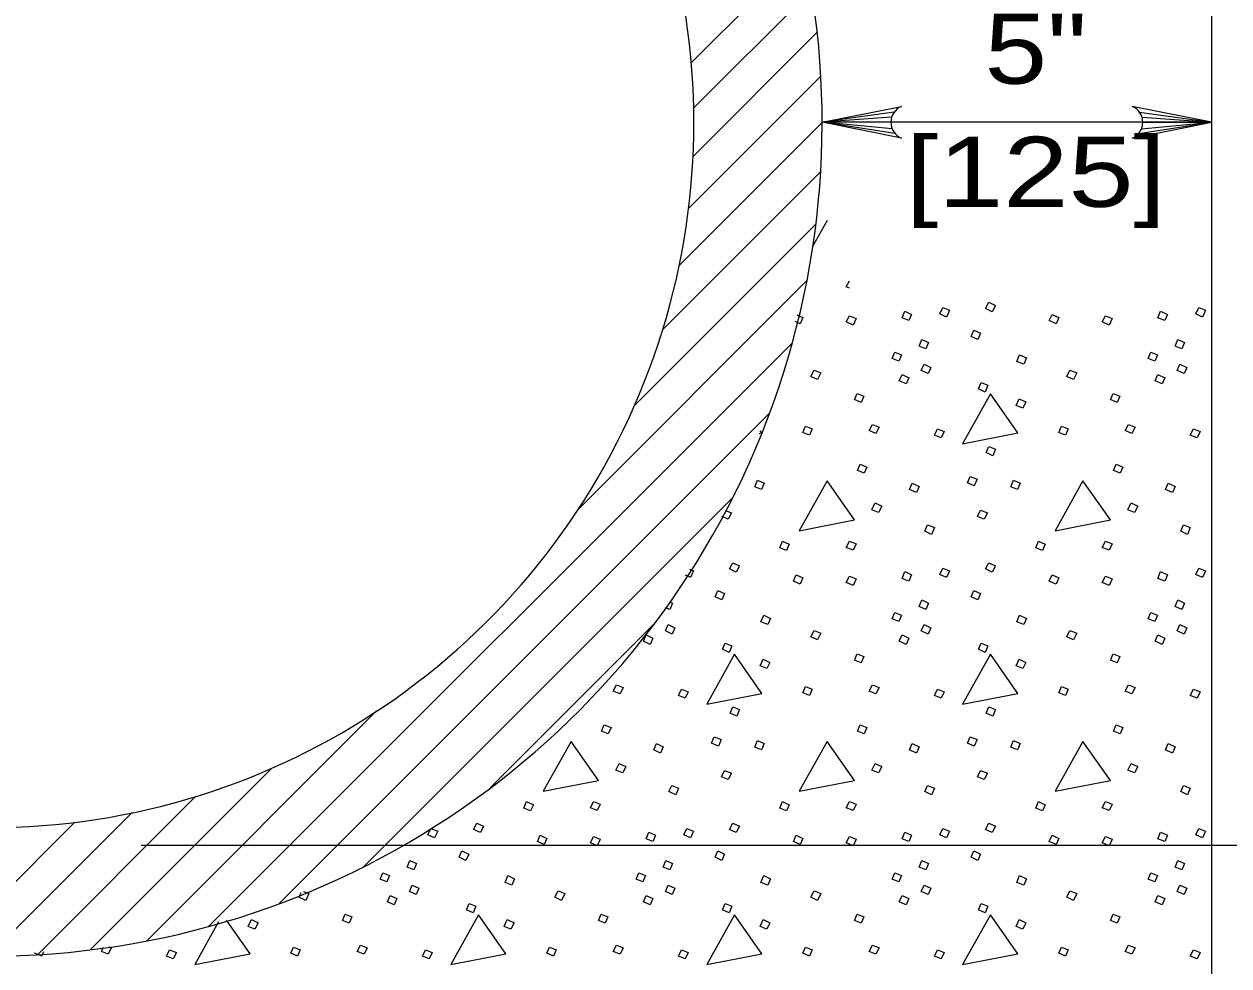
# Model space of a CAD drawing. Extents: x 1036.7 to 1070.7, y 883.9 to 905.9.
# Drawn here: x 1054.169 to 1056.851, y 894.74 to 896.836 of the extents above; entities that cross this region are included whole.
import ezdxf
from ezdxf.enums import TextEntityAlignment as Align

# ---------------------------------------------------------------- set-up
doc = ezdxf.new("R2010")
doc.units = 0
doc.header["$LTSCALE"] = 0.062
doc.layers.add('1', color=7, linetype='Continuous', lineweight=13)

msp = doc.modelspace()

# ---------------------------------------------------------------- linework, layer by layer
at = {"layer": '1'}
for p, q in [((1055.65425, 896.74975), (1055.90517, 897.00058)), ((1055.65967, 896.64908), (1055.92167, 896.911)), ((1055.65833, 896.54175), (1055.93425, 896.81758)), ((1055.64792, 896.42533), (1055.94225, 896.71958)), ((1055.62667, 896.29817), (1055.94508, 896.61633)), ((1056.106, 896.64), (1055.94575, 896.61758)), ((1056.1005, 896.62892), (1055.94575, 896.61758)), ((1056.09892, 896.61758), (1055.94575, 896.61758)), ((1056.10175, 896.60325), (1055.94575, 896.61758)), ((1056.10783, 896.59283), (1055.94575, 896.61758)), ((1056.65058, 896.59283), (1056.81275, 896.61758)), ((1056.6525, 896.64), (1056.81275, 896.61758)), ((1056.65675, 896.60325), (1056.81275, 896.61758)), ((1056.65792, 896.62892), (1056.81275, 896.61758)), ((1056.65958, 896.61758), (1056.81275, 896.61758)), ((1055.59083, 896.15625), (1055.94175, 896.50708)), ((1055.52825, 895.98758), (1055.93108, 896.39033)), ((1055.95667, 896.399), (1055.9235, 896.33958)), ((1055.40108, 895.75442), (1055.91125, 896.26458)), ((1054.58083, 894.82842), (1055.87942, 896.12683)), ((1054.73742, 894.87892), (1055.82817, 895.9695)), ((1054.92558, 894.96108), (1055.74567, 895.781)), ((1055.20725, 895.13667), (1055.57117, 895.5005)), ((1054.44258, 894.79608), (1054.95308, 895.30658)), ((1054.31633, 894.77583), (1054.72, 895.17942)), ((1054.19933, 894.76483), (1054.552, 895.1175)), ((1054.09, 894.7615), (1054.40967, 895.08117)), ((1053.987, 894.7645), (1054.28267, 895.06017)), ((1058.42608, 895.00783), (1054.42967, 895.00783))]:
    msp.add_line(p, q, dxfattribs=at)
at = {"layer": '1', "lineweight": 25}
msp.add_lwpolyline([(1056.21542, 900.486), (1056.21542, 899.32858), (1056.81275, 899.32858), (1056.81275, 893.80992)], dxfattribs=at)
at = {"layer": '1'}
for points in [[(1056.12275, 896.58225), (1055.94575, 896.61758), (1056.12275, 896.653)], [(1056.63575, 896.58225), (1056.81275, 896.61758), (1056.63575, 896.653)], [(1056.81275, 896.61758), (1056.53767, 896.61758), (1055.94575, 896.61758)], [(1056.00642, 896.24833), (1055.99958, 896.25108), (1056.00642, 896.26475)], [(1055.88975, 896.18908), (1055.90267, 896.18308), (1055.89667, 896.16917), (1055.88608, 896.17408)], [(1055.80567, 895.92508), (1055.81167, 895.92625), (1055.80817, 895.93117)], [(1055.73067, 895.75358), (1055.74375, 895.74833), (1055.73675, 895.73442), (1055.72242, 895.74017)], [(1055.65033, 895.62317), (1055.65975, 895.61942), (1055.65275, 895.60442), (1055.64192, 895.6095)], [(1055.60575, 895.55075), (1055.61275, 895.5475), (1055.60683, 895.5335), (1055.59742, 895.53725)], [(1054.7915, 894.9055), (1054.80317, 894.90083), (1054.79617, 894.88583), (1054.78117, 894.89283), (1054.7865, 894.90342)], [(1054.60217, 894.83767), (1054.54933, 894.74292), (1054.67225, 894.76692), (1054.61967, 894.84192)], [(1054.21233, 894.77117), (1054.20842, 894.76192), (1054.1935, 894.76792), (1054.19417, 894.76975)], [(1054.357, 894.7825), (1054.36342, 894.77992), (1054.35642, 894.76592), (1054.34142, 894.77192), (1054.34625, 894.78167)]]:
    msp.add_lwpolyline(points, dxfattribs=at)
for points in [[(1056.3165, 896.21708), (1056.33142, 896.21008), (1056.32442, 896.19608), (1056.3095, 896.20308)], [(1056.12958, 896.19708), (1056.1445, 896.19008), (1056.13858, 896.17617), (1056.12358, 896.18208)], [(1056.2145, 896.20508), (1056.2295, 896.19908), (1056.2225, 896.18408), (1056.2075, 896.19108)], [(1056.45742, 896.19008), (1056.47242, 896.18308), (1056.46642, 896.16917), (1056.45142, 896.17617)], [(1056.69925, 896.19708), (1056.71425, 896.19008), (1056.70825, 896.17617), (1056.69325, 896.18208)], [(1056.78425, 896.20508), (1056.79925, 896.19908), (1056.79225, 896.18408), (1056.77725, 896.19108)], [(1056.00658, 896.18708), (1056.02158, 896.18108), (1056.01458, 896.16617), (1055.99958, 896.17317)], [(1056.57633, 896.18708), (1056.59133, 896.18108), (1056.58433, 896.16617), (1056.56933, 896.17317)], [(1056.1675, 896.13417), (1056.1825, 896.12717), (1056.1765, 896.11317), (1056.1615, 896.11917)], [(1056.2835, 896.15517), (1056.2985, 896.14817), (1056.2925, 896.13417), (1056.2775, 896.14117)], [(1056.73725, 896.13417), (1056.75225, 896.12717), (1056.74625, 896.11317), (1056.73125, 896.11917)], [(1056.10758, 896.10617), (1056.12258, 896.10017), (1056.11658, 896.08617), (1056.10158, 896.09217)], [(1056.38542, 896.10017), (1056.40042, 896.09317), (1056.39442, 896.07917), (1056.37942, 896.08517)], [(1056.67725, 896.10617), (1056.69225, 896.10017), (1056.68625, 896.08617), (1056.67125, 896.09217)], [(1055.92767, 896.06617), (1055.94267, 896.06017), (1055.93567, 896.04517), (1055.92067, 896.05217)], [(1056.12358, 896.05617), (1056.13858, 896.04917), (1056.13258, 896.03517), (1056.11758, 896.04217)], [(1056.1725, 896.07917), (1056.1875, 896.07217), (1056.1815, 896.05817), (1056.1665, 896.06517)], [(1056.49733, 896.06617), (1056.51233, 896.06017), (1056.50533, 896.04517), (1056.49042, 896.05217)], [(1056.69325, 896.05617), (1056.70825, 896.04917), (1056.70225, 896.03517), (1056.68725, 896.04217)], [(1056.74225, 896.07917), (1056.75725, 896.07217), (1056.75125, 896.05817), (1056.73625, 896.06517)], [(1056.2995, 896.03817), (1056.31442, 896.03225), (1056.3085, 896.01725), (1056.2935, 896.02425)], [(1056.02358, 896.01425), (1056.03858, 896.00825), (1056.03258, 895.99425), (1056.01758, 896.00025)], [(1056.32042, 896.01325), (1056.2585, 895.90225), (1056.38142, 895.92625)], [(1056.38442, 896.00225), (1056.39942, 895.99525), (1056.39242, 895.98125), (1056.37742, 895.98725)], [(1056.59333, 896.01425), (1056.60833, 896.00825), (1056.60233, 895.99425), (1056.58733, 896.00025)], [(1055.90867, 895.94125), (1055.92367, 895.93525), (1055.91767, 895.92125), (1055.90267, 895.92725)], [(1056.05758, 895.94525), (1056.07258, 895.93925), (1056.06558, 895.92525), (1056.05058, 895.93125)], [(1056.2025, 895.93525), (1056.2175, 895.92925), (1056.2105, 895.91525), (1056.1955, 895.92125)], [(1056.47842, 895.94125), (1056.49333, 895.93525), (1056.48742, 895.92125), (1056.47242, 895.92725)], [(1056.62733, 895.94525), (1056.64233, 895.93925), (1056.63533, 895.92525), (1056.62033, 895.93125)], [(1056.77225, 895.93525), (1056.78725, 895.92925), (1056.78025, 895.91525), (1056.76525, 895.92125)], [(1056.3165, 895.89625), (1056.33142, 895.89033), (1056.32542, 895.87533), (1056.3105, 895.88233)], [(1056.03058, 895.85633), (1056.04558, 895.85033), (1056.03958, 895.83633), (1056.02458, 895.84233)], [(1056.60033, 895.85633), (1056.61533, 895.85033), (1056.60933, 895.83633), (1056.59433, 895.84233)], [(1055.80167, 895.82133), (1055.81667, 895.81433), (1055.81067, 895.80033), (1055.79567, 895.80633)], [(1055.95667, 895.81933), (1055.89467, 895.70842), (1056.01758, 895.73242)], [(1056.1465, 895.81433), (1056.1615, 895.80733), (1056.1555, 895.79333), (1056.1405, 895.80033)], [(1056.2755, 895.82933), (1056.2905, 895.82333), (1056.2845, 895.80833), (1056.2695, 895.81533)], [(1056.37142, 895.82133), (1056.38642, 895.81433), (1056.38042, 895.80033), (1056.36542, 895.80633)], [(1056.52633, 895.81933), (1056.46442, 895.70842), (1056.58733, 895.73242)], [(1056.71625, 895.81433), (1056.73125, 895.80733), (1056.72525, 895.79333), (1056.71025, 895.80033)], [(1056.06358, 895.77033), (1056.07858, 895.76333), (1056.07158, 895.74933), (1056.05658, 895.75533)], [(1056.63333, 895.77033), (1056.64833, 895.76333), (1056.64133, 895.74933), (1056.62633, 895.75533)], [(1056.2985, 895.75433), (1056.3135, 895.74833), (1056.3065, 895.73442), (1056.2915, 895.74042)], [(1056.1805, 895.72142), (1056.1955, 895.71542), (1056.1895, 895.70042), (1056.1745, 895.70742)], [(1056.75025, 895.72142), (1056.76525, 895.71542), (1056.75925, 895.70042), (1056.74425, 895.70742)], [(1055.85767, 895.68542), (1055.87267, 895.67842), (1055.86667, 895.66442), (1055.85167, 895.67042)], [(1056.00658, 895.68542), (1056.02158, 895.67942), (1056.01458, 895.66542), (1055.99958, 895.67142)], [(1056.42742, 895.68542), (1056.44242, 895.67842), (1056.43642, 895.66442), (1056.42142, 895.67042)], [(1056.57633, 895.68542), (1056.59133, 895.67942), (1056.58433, 895.66542), (1056.56933, 895.67142)], [(1055.74675, 895.63742), (1055.76175, 895.63042), (1055.75475, 895.61642), (1055.73975, 895.62342)], [(1056.2145, 895.62542), (1056.2295, 895.61942), (1056.2225, 895.60442), (1056.2075, 895.61142)], [(1056.3165, 895.63742), (1056.33142, 895.63042), (1056.32442, 895.61642), (1056.3095, 895.62342)], [(1056.78425, 895.62542), (1056.79925, 895.61942), (1056.79225, 895.60442), (1056.77725, 895.61142)], [(1055.88767, 895.61042), (1055.90267, 895.60342), (1055.89667, 895.5895), (1055.88167, 895.5965)], [(1056.00658, 895.60742), (1056.02158, 895.60142), (1056.01458, 895.5865), (1055.99958, 895.5935)], [(1056.12958, 895.61742), (1056.1445, 895.61042), (1056.13858, 895.5965), (1056.12358, 895.60242)], [(1056.45742, 895.61042), (1056.47242, 895.60342), (1056.46642, 895.5895), (1056.45142, 895.5965)], [(1056.57633, 895.60742), (1056.59133, 895.60142), (1056.58433, 895.5865), (1056.56933, 895.5935)], [(1056.69925, 895.61742), (1056.71425, 895.61042), (1056.70825, 895.5965), (1056.69325, 895.60242)], [(1055.71375, 895.5755), (1055.72875, 895.5685), (1055.72275, 895.5545), (1055.70775, 895.5615)], [(1056.2835, 895.5755), (1056.2985, 895.5685), (1056.2925, 895.5545), (1056.2775, 895.5615)], [(1056.1675, 895.5545), (1056.1825, 895.5475), (1056.1765, 895.5335), (1056.1615, 895.5395)], [(1056.73725, 895.5545), (1056.75225, 895.5475), (1056.74625, 895.5335), (1056.73125, 895.5395)], [(1055.81567, 895.5205), (1055.83067, 895.5135), (1055.82467, 895.4995), (1055.80967, 895.5055)], [(1056.10758, 895.5265), (1056.12258, 895.5205), (1056.11658, 895.5065), (1056.10158, 895.5125)], [(1056.38542, 895.5205), (1056.40042, 895.5135), (1056.39442, 895.4995), (1056.37942, 895.5055)], [(1056.67725, 895.5265), (1056.69225, 895.5205), (1056.68625, 895.5065), (1056.67125, 895.5125)], [(1055.60283, 895.4995), (1055.61775, 895.4925), (1055.61175, 895.4785), (1055.59683, 895.4855)], [(1056.1725, 895.4995), (1056.1875, 895.4925), (1056.1815, 895.4785), (1056.1665, 895.4855)], [(1056.74225, 895.4995), (1056.75725, 895.4925), (1056.75125, 895.4785), (1056.73625, 895.4855)], [(1055.55383, 895.4765), (1055.56883, 895.4695), (1055.56283, 895.4555), (1055.54783, 895.4625)], [(1055.92767, 895.4865), (1055.94267, 895.4805), (1055.93567, 895.4655), (1055.92067, 895.4725)], [(1056.12358, 895.4765), (1056.13858, 895.4695), (1056.13258, 895.4555), (1056.11758, 895.4625)], [(1056.49733, 895.4865), (1056.51233, 895.4805), (1056.50533, 895.4655), (1056.49042, 895.4725)], [(1056.69325, 895.4765), (1056.70825, 895.4695), (1056.70225, 895.4555), (1056.68725, 895.4625)], [(1055.72975, 895.4585), (1055.74475, 895.45258), (1055.73875, 895.43758), (1055.72375, 895.44458)], [(1056.2995, 895.4585), (1056.31442, 895.45258), (1056.3085, 895.43758), (1056.2935, 895.44458)], [(1055.75075, 895.43358), (1055.68875, 895.32258), (1055.81167, 895.34658)], [(1055.81467, 895.42258), (1055.82967, 895.41558), (1055.82267, 895.40158), (1055.80767, 895.40758)], [(1056.02358, 895.43458), (1056.03858, 895.42858), (1056.03258, 895.41458), (1056.01758, 895.42058)], [(1056.32042, 895.43358), (1056.2585, 895.32258), (1056.38142, 895.34658)], [(1056.38442, 895.42258), (1056.39942, 895.41558), (1056.39242, 895.40158), (1056.37742, 895.40758)], [(1056.59333, 895.43458), (1056.60833, 895.42858), (1056.60233, 895.41458), (1056.58733, 895.42058)], [(1055.48783, 895.36558), (1055.50283, 895.35958), (1055.49583, 895.34558), (1055.48083, 895.35158)], [(1055.90867, 895.36158), (1055.92367, 895.35558), (1055.91767, 895.34158), (1055.90267, 895.34758)], [(1056.05758, 895.36558), (1056.07258, 895.35958), (1056.06558, 895.34558), (1056.05058, 895.35158)], [(1056.47842, 895.36158), (1056.49333, 895.35558), (1056.48742, 895.34158), (1056.47242, 895.34758)], [(1056.62733, 895.36558), (1056.64233, 895.35958), (1056.63533, 895.34558), (1056.62033, 895.35158)], [(1055.63275, 895.35558), (1055.64775, 895.34958), (1055.64075, 895.33558), (1055.62575, 895.34158)], [(1056.2025, 895.35558), (1056.2175, 895.34958), (1056.2105, 895.33558), (1056.1955, 895.34158)], [(1056.77225, 895.35558), (1056.78725, 895.34958), (1056.78025, 895.33558), (1056.76525, 895.34158)], [(1055.74675, 895.31658), (1055.76175, 895.31058), (1055.75575, 895.29567), (1055.74075, 895.30267)], [(1056.3165, 895.31658), (1056.33142, 895.31058), (1056.32542, 895.29567), (1056.3105, 895.30267)], [(1055.46083, 895.27667), (1055.47583, 895.27067), (1055.46983, 895.25667), (1055.45483, 895.26267)], [(1056.03058, 895.27667), (1056.04558, 895.27067), (1056.03958, 895.25667), (1056.02458, 895.26267)], [(1056.60033, 895.27667), (1056.61533, 895.27067), (1056.60933, 895.25667), (1056.59433, 895.26267)], [(1055.70575, 895.24967), (1055.72075, 895.24367), (1055.71475, 895.22867), (1055.69975, 895.23567)], [(1056.2755, 895.24967), (1056.2905, 895.24367), (1056.2845, 895.22867), (1056.2695, 895.23567)], [(1055.38692, 895.23967), (1055.32492, 895.12875), (1055.44783, 895.15275)], [(1055.57683, 895.23467), (1055.59183, 895.22767), (1055.58583, 895.21367), (1055.57083, 895.22067)], [(1055.80167, 895.24167), (1055.81667, 895.23467), (1055.81067, 895.22067), (1055.79567, 895.22667)], [(1055.95667, 895.23967), (1055.89467, 895.12875), (1056.01758, 895.15275)], [(1056.1465, 895.23467), (1056.1615, 895.22767), (1056.1555, 895.21367), (1056.1405, 895.22067)], [(1056.37142, 895.24167), (1056.38642, 895.23467), (1056.38042, 895.22067), (1056.36542, 895.22667)], [(1056.52633, 895.23967), (1056.46442, 895.12875), (1056.58733, 895.15275)], [(1056.71625, 895.23467), (1056.73125, 895.22767), (1056.72525, 895.21367), (1056.71025, 895.22067)], [(1055.49383, 895.19067), (1055.50883, 895.18367), (1055.50183, 895.16967), (1055.48683, 895.17567)], [(1055.72875, 895.17467), (1055.74375, 895.16867), (1055.73675, 895.15475), (1055.72175, 895.16075)], [(1056.06358, 895.19067), (1056.07858, 895.18367), (1056.07158, 895.16967), (1056.05658, 895.17567)], [(1056.2985, 895.17467), (1056.3135, 895.16867), (1056.3065, 895.15475), (1056.2915, 895.16075)], [(1056.63333, 895.19067), (1056.64833, 895.18367), (1056.64133, 895.16967), (1056.62633, 895.17567)], [(1055.61083, 895.14175), (1055.62575, 895.13575), (1055.61975, 895.12075), (1055.60483, 895.12775)], [(1056.1805, 895.14175), (1056.1955, 895.13575), (1056.1895, 895.12075), (1056.1745, 895.12775)], [(1056.75025, 895.14175), (1056.76525, 895.13575), (1056.75925, 895.12075), (1056.74425, 895.12775)], [(1055.28792, 895.10575), (1055.30292, 895.09875), (1055.29692, 895.08475), (1055.28192, 895.09075)], [(1055.43683, 895.10575), (1055.45183, 895.09975), (1055.44483, 895.08575), (1055.42983, 895.09175)], [(1055.85767, 895.10575), (1055.87267, 895.09875), (1055.86667, 895.08475), (1055.85167, 895.09075)], [(1056.00658, 895.10575), (1056.02158, 895.09975), (1056.01458, 895.08575), (1055.99958, 895.09175)], [(1056.42742, 895.10575), (1056.44242, 895.09875), (1056.43642, 895.08475), (1056.42142, 895.09075)], [(1056.57633, 895.10575), (1056.59133, 895.09975), (1056.58433, 895.08575), (1056.56933, 895.09175)], [(1055.07508, 895.04575), (1055.09, 895.03975), (1055.083, 895.02475), (1055.06808, 895.03175)], [(1055.177, 895.05775), (1055.192, 895.05075), (1055.185, 895.03675), (1055.17, 895.04375)], [(1055.55983, 895.03775), (1055.57483, 895.03075), (1055.56883, 895.01683), (1055.55383, 895.02275)], [(1055.64475, 895.04575), (1055.65975, 895.03975), (1055.65275, 895.02475), (1055.63775, 895.03175)], [(1055.74675, 895.05775), (1055.76175, 895.05075), (1055.75475, 895.03675), (1055.73975, 895.04375)], [(1056.12958, 895.03775), (1056.1445, 895.03075), (1056.13858, 895.01683), (1056.12358, 895.02275)], [(1056.2145, 895.04575), (1056.2295, 895.03975), (1056.2225, 895.02475), (1056.2075, 895.03175)], [(1056.3165, 895.05775), (1056.33142, 895.05075), (1056.32442, 895.03675), (1056.3095, 895.04375)], [(1056.69925, 895.03775), (1056.71425, 895.03075), (1056.70825, 895.01683), (1056.69325, 895.02275)], [(1056.78425, 895.04575), (1056.79925, 895.03975), (1056.79225, 895.02475), (1056.77725, 895.03175)], [(1055.31792, 895.03075), (1055.33292, 895.02375), (1055.32692, 895.00983), (1055.31192, 895.01683)], [(1055.43683, 895.02775), (1055.45183, 895.02183), (1055.44483, 895.00683), (1055.42983, 895.01383)], [(1055.88767, 895.03075), (1055.90267, 895.02375), (1055.89667, 895.00983), (1055.88167, 895.01683)], [(1056.00658, 895.02775), (1056.02158, 895.02183), (1056.01458, 895.00683), (1055.99958, 895.01383)], [(1056.45742, 895.03075), (1056.47242, 895.02375), (1056.46642, 895.00983), (1056.45142, 895.01683)], [(1056.57633, 895.02775), (1056.59133, 895.02183), (1056.58433, 895.00683), (1056.56933, 895.01383)], [(1055.144, 894.99583), (1055.159, 894.98883), (1055.153, 894.97483), (1055.138, 894.98183)], [(1055.71375, 894.99583), (1055.72875, 894.98883), (1055.72275, 894.97483), (1055.70775, 894.98183)], [(1056.2835, 894.99583), (1056.2985, 894.98883), (1056.2925, 894.97483), (1056.2775, 894.98183)], [(1055.02808, 894.97483), (1055.04308, 894.96783), (1055.03708, 894.95383), (1055.02208, 894.95983)], [(1055.59783, 894.97483), (1055.61275, 894.96783), (1055.60683, 894.95383), (1055.59183, 894.95983)], [(1056.1675, 894.97483), (1056.1825, 894.96783), (1056.1765, 894.95383), (1056.1615, 894.95983)], [(1056.73725, 894.97483), (1056.75225, 894.96783), (1056.74625, 894.95383), (1056.73125, 894.95983)], [(1054.96808, 894.94683), (1054.98308, 894.94083), (1054.97708, 894.92683), (1054.96208, 894.93283)], [(1055.246, 894.94083), (1055.26092, 894.93383), (1055.255, 894.91983), (1055.24, 894.92583)], [(1055.53783, 894.94683), (1055.55283, 894.94083), (1055.54683, 894.92683), (1055.53183, 894.93283)], [(1055.81567, 894.94083), (1055.83067, 894.93383), (1055.82467, 894.91983), (1055.80967, 894.92583)], [(1056.10758, 894.94683), (1056.12258, 894.94083), (1056.11658, 894.92683), (1056.10158, 894.93283)], [(1056.38542, 894.94083), (1056.40042, 894.93383), (1056.39442, 894.91983), (1056.37942, 894.92583)], [(1056.67725, 894.94683), (1056.69225, 894.94083), (1056.68625, 894.92683), (1056.67125, 894.93283)], [(1055.03308, 894.91983), (1055.04808, 894.91283), (1055.04208, 894.89883), (1055.02708, 894.90583)], [(1055.35792, 894.90683), (1055.37292, 894.90083), (1055.36592, 894.88583), (1055.35092, 894.89283)], [(1055.60283, 894.91983), (1055.61775, 894.91283), (1055.61175, 894.89883), (1055.59683, 894.90583)], [(1055.92767, 894.90683), (1055.94267, 894.90083), (1055.93567, 894.88583), (1055.92067, 894.89283)], [(1056.1725, 894.91983), (1056.1875, 894.91283), (1056.1815, 894.89883), (1056.1665, 894.90583)], [(1056.49733, 894.90683), (1056.51233, 894.90083), (1056.50533, 894.88583), (1056.49042, 894.89283)], [(1056.74225, 894.91983), (1056.75725, 894.91283), (1056.75125, 894.89883), (1056.73625, 894.90583)], [(1054.98408, 894.89683), (1054.99908, 894.88983), (1054.99308, 894.87583), (1054.97808, 894.88283)], [(1055.16, 894.87883), (1055.175, 894.87292), (1055.169, 894.85792), (1055.154, 894.86492)], [(1055.55383, 894.89683), (1055.56883, 894.88983), (1055.56283, 894.87583), (1055.54783, 894.88283)], [(1055.72975, 894.87883), (1055.74475, 894.87292), (1055.73875, 894.85792), (1055.72375, 894.86492)], [(1056.12358, 894.89683), (1056.13858, 894.88983), (1056.13258, 894.87583), (1056.11758, 894.88283)], [(1056.2995, 894.87883), (1056.31442, 894.87292), (1056.3085, 894.85792), (1056.2935, 894.86492)], [(1056.69325, 894.89683), (1056.70825, 894.88983), (1056.70225, 894.87583), (1056.68725, 894.88283)], [(1054.88417, 894.85492), (1054.89917, 894.84892), (1054.89317, 894.83492), (1054.87817, 894.84092)], [(1055.181, 894.85392), (1055.119, 894.74292), (1055.242, 894.76692)], [(1055.45383, 894.85492), (1055.46883, 894.84892), (1055.46283, 894.83492), (1055.44783, 894.84092)], [(1055.75075, 894.85392), (1055.68875, 894.74292), (1055.81167, 894.76692)], [(1056.02358, 894.85492), (1056.03858, 894.84892), (1056.03258, 894.83492), (1056.01758, 894.84092)], [(1056.32042, 894.85392), (1056.2585, 894.74292), (1056.38142, 894.76692)], [(1056.59333, 894.85492), (1056.60833, 894.84892), (1056.60233, 894.83492), (1056.58733, 894.84092)], [(1054.67525, 894.84292), (1054.69025, 894.83592), (1054.68325, 894.82192), (1054.66825, 894.82792)], [(1055.245, 894.84292), (1055.25992, 894.83592), (1055.25292, 894.82192), (1055.238, 894.82792)], [(1055.81467, 894.84292), (1055.82967, 894.83592), (1055.82267, 894.82192), (1055.80767, 894.82792)], [(1056.38442, 894.84292), (1056.39942, 894.83592), (1056.39242, 894.82192), (1056.37742, 894.82792)], [(1054.49333, 894.77592), (1054.50833, 894.76992), (1054.50133, 894.75592), (1054.48633, 894.76192)], [(1054.76917, 894.78192), (1054.78417, 894.77592), (1054.77817, 894.76192), (1054.76317, 894.76792)], [(1054.91808, 894.78592), (1054.93308, 894.77992), (1054.92608, 894.76592), (1054.91108, 894.77192)], [(1055.06308, 894.77592), (1055.07808, 894.76992), (1055.07108, 894.75592), (1055.05608, 894.76192)], [(1055.33892, 894.78192), (1055.35392, 894.77592), (1055.34792, 894.76192), (1055.33292, 894.76792)], [(1055.48783, 894.78592), (1055.50283, 894.77992), (1055.49583, 894.76592), (1055.48083, 894.77192)], [(1055.63275, 894.77592), (1055.64775, 894.76992), (1055.64075, 894.75592), (1055.62575, 894.76192)], [(1055.90867, 894.78192), (1055.92367, 894.77592), (1055.91767, 894.76192), (1055.90267, 894.76792)], [(1056.05758, 894.78592), (1056.07258, 894.77992), (1056.06558, 894.76592), (1056.05058, 894.77192)], [(1056.2025, 894.77592), (1056.2175, 894.76992), (1056.2105, 894.75592), (1056.1955, 894.76192)], [(1056.47842, 894.78192), (1056.49333, 894.77592), (1056.48742, 894.76192), (1056.47242, 894.76792)], [(1056.62733, 894.78592), (1056.64233, 894.77992), (1056.63533, 894.76592), (1056.62033, 894.77192)], [(1056.77225, 894.77592), (1056.78725, 894.76992), (1056.78025, 894.75592), (1056.76525, 894.76192)]]:
    msp.add_lwpolyline(points, close=True, dxfattribs=at)
for centre, start, end in [((1056.13701, 896.61766), 112.08782, 247.91395), ((1056.62143, 896.61766), 292.08605, 67.91218)]:
    msp.add_arc(centre, 0.0382, start, end, dxfattribs=at)
at = {"layer": '1', "lineweight": 25}
for centre, major_axis, start_param, end_param in [((1054.08944, 896.61762), (1.8563, 0), 4.7123821, 7.1267519), ((1054.09071, 896.61711), (1.56952, 0), 4.7123633, 7.1023478)]:
    msp.add_ellipse(centre, major_axis=major_axis, ratio=0.999895, start_param=start_param, end_param=end_param, dxfattribs=at)

# ---------------------------------------------------------------- texts
at = {"layer": '1'}
for s, width, p in [('5"', 1.2, (1056.42146, 896.70342)), ('[125]', 1.25, (1056.42142, 896.42942))]:
    msp.add_text(s, height=0.156, dxfattribs=dict(at, width=width)).set_placement(p, align=Align.CENTER)

doc.saveas('drawing.dxf')
